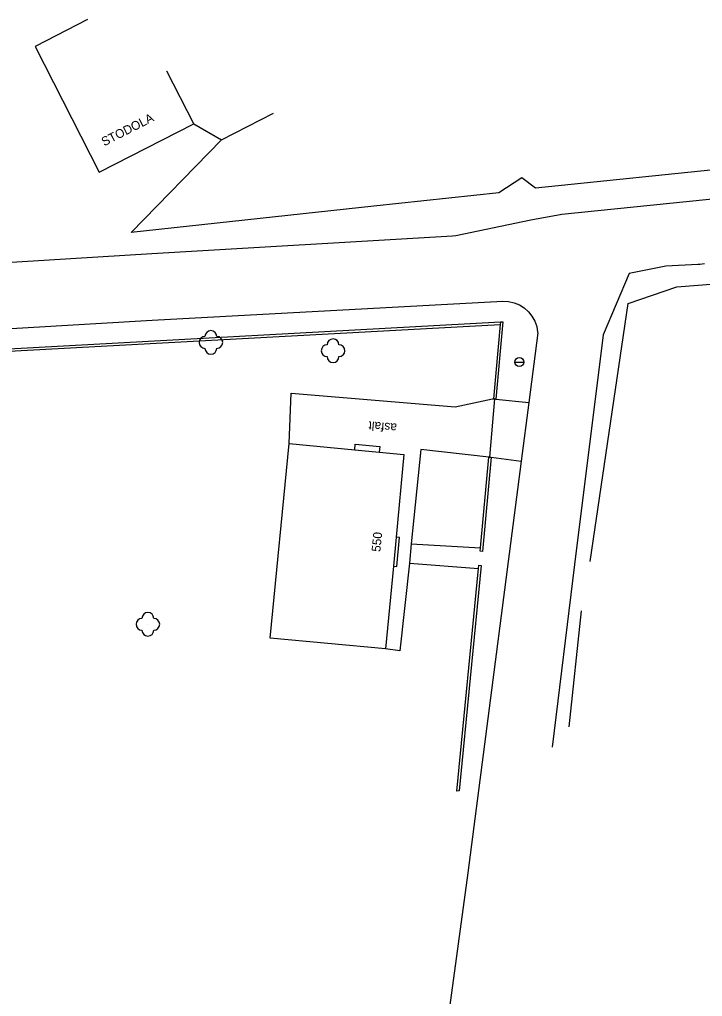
# Model space of a CAD drawing. Extents: x -536391 to -535419, y -1201788 to -1200779.
# Drawn here: x -535647.8 to -535590.1, y -1201668.6 to -1201586 of the extents above; entities that cross this region are included whole.
import ezdxf

# ---------------------------------------------------------------- set-up
doc = ezdxf.new("R2010")
doc.units = 0
for name, color, linetype in [('BUDOVY_MĚŘ', 7, 'Continuous'), ('POMOC_POPIS', 7, 'Continuous'), ('ROZHRANÍ_PLOCH', 7, 'Continuous'), ('ZELEŇ', 7, 'Continuous'), ('ZN_DOPLŇKOVÉ', 7, 'Continuous'), ('Č_POPIS_ORIENT', 7, 'Continuous')]:
    doc.layers.add(name, color=color, linetype=linetype)

msp = doc.modelspace()

# ---------------------------------------------------------------- linework, layer by layer
at = {"layer": 'BUDOVY_MĚŘ'}
for points in [[(-535642.06, -1201585.96), (-535646.51, -1201588.24), (-535641.1, -1201598.86), (-535633.08, -1201594.77)], [(-535633.08, -1201594.77), (-535635.36, -1201590.32)], [(-535616.86, -1201639.18), (-535626.62, -1201638.27), (-535625.02, -1201621.81)], [(-535625.02, -1201621.81), (-535619.47, -1201622.35)], [(-535619.47, -1201622.35), (-535617.4, -1201622.55)], [(-535617.4, -1201622.55), (-535615.32, -1201622.75), (-535615.98, -1201629.74)], [(-535615.98, -1201629.74), (-535616.21, -1201632.2)], [(-535616.21, -1201632.2), (-535616.86, -1201639.18)]]:
    msp.add_lwpolyline(points, dxfattribs=at)
at = {"layer": 'ROZHRANÍ_PLOCH'}
for points in [[(-535586.73, -1201600.91), (-535601.96, -1201602.45), (-535604.58, -1201602.94), (-535610.94, -1201604.25), (-535611.21, -1201604.27), (-535636.62, -1201605.79), (-535670.91, -1201607.88)], [(-535593.16, -1201606.83), (-535596.27, -1201607.45), (-535598.47, -1201612.63), (-535600.88, -1201632.06), (-535602.77, -1201647.49)], [(-535589.91, -1201606.63), (-535590.1, -1201606.65), (-535590.29, -1201606.67), (-535590.47, -1201606.69), (-535593.16, -1201606.83)], [(-535670.5, -1201613.38), (-535636.6, -1201611.38), (-535606.94, -1201609.77), (-535606.46, -1201609.81), (-535605.99, -1201609.92), (-535605.55, -1201610.1), (-535605.15, -1201610.35), (-535604.79, -1201610.67), (-535604.49, -1201611.05), (-535604.25, -1201611.46), (-535604.09, -1201611.92), (-535604.01, -1201612.39), (-535604, -1201612.47), (-535604.76, -1201618.34)], [(-535625.02, -1201621.81), (-535624.85, -1201617.57), (-535610.99, -1201618.72), (-535607.83, -1201618.05), (-535607.73, -1201618.04)], [(-535607.53, -1201618.06), (-535604.76, -1201618.34)], [(-535604.76, -1201618.34), (-535605.4, -1201623.3)], [(-535619.47, -1201622.35), (-535619.43, -1201621.87), (-535617.35, -1201622.07), (-535617.4, -1201622.55)], [(-535608.13, -1201622.96), (-535613.9, -1201622.33), (-535614.7, -1201630.29)], [(-535605.4, -1201623.3), (-535609.91, -1201658.13), (-535616.63, -1201707.41), (-535624.28, -1201765.57), (-535626.89, -1201785.62), (-535627.19, -1201786.05), (-535627.78, -1201786.76), (-535628.42, -1201787.43), (-535629.12, -1201788.03), (-535629.31, -1201788.17)], [(-535607.93, -1201622.98), (-535605.4, -1201623.3)], [(-535616.21, -1201632.2), (-535615.92, -1201632.23), (-535615.68, -1201629.77), (-535615.98, -1201629.74)], [(-535614.7, -1201630.29), (-535614.85, -1201631.95)], [(-535614.7, -1201630.29), (-535608.85, -1201630.64)], [(-535614.85, -1201631.95), (-535615.65, -1201639.36), (-535616.86, -1201639.18)], [(-535614.85, -1201631.95), (-535609.02, -1201632.39)]]:
    msp.add_lwpolyline(points, dxfattribs=at)
at = {"layer": 'ZELEŇ'}
for centre in [(-535631.64, -1201613.27), (-535621.31, -1201613.97), (-535636.97, -1201637.11)]:
    msp.add_circle(centre, 0.0005, dxfattribs=at)
for centre, start, end in [((-535631.64, -1201612.77), 0, 179.99999), ((-535632.14, -1201613.27), 89.99999, 269.99999), ((-535631.14, -1201613.27), 270, 89.99999), ((-535621.81, -1201613.97), 89.99999, 269.99999), ((-535621.31, -1201613.47), 0, 179.99999), ((-535620.81, -1201613.97), 270, 89.99999), ((-535631.64, -1201613.77), 179.99999, 359.99999), ((-535621.31, -1201614.47), 179.99999, 359.99999), ((-535637.47, -1201637.11), 89.99999, 269.99999), ((-535636.97, -1201636.61), 0, 179.99999), ((-535636.47, -1201637.11), 270, 89.99999), ((-535636.97, -1201637.61), 179.99999, 359.99999)]:
    msp.add_arc(centre, 0.5, start, end, dxfattribs=at)
at = {"layer": 'ZN_DOPLŇKOVÉ'}
msp.add_line((-535605.935, -1201614.93), (-535605.185, -1201614.93), dxfattribs=at)
for points in [[(-535572.12, -1201588.65), (-535571.35, -1201590.42), (-535577.76, -1201593.75), (-535587.2, -1201598.48), (-535604.18, -1201600.22)], [(-535630.75, -1201596.13), (-535626.34, -1201593.87)], [(-535633.08, -1201594.77), (-535630.75, -1201596.13)], [(-535604.18, -1201600.22), (-535605.35, -1201599.35), (-535607.29, -1201600.63), (-535617.85, -1201601.75), (-535638.39, -1201603.96), (-535630.75, -1201596.13)], [(-535592.23, -1201608.58), (-535584.33, -1201607.95), (-535556.13, -1201605.24)], [(-535599.58, -1201631.8), (-535596.35, -1201609.97), (-535592.23, -1201608.58)], [(-535649.24, -1201614.05), (-535607.18, -1201611.74)], [(-535649.22, -1201613.85), (-535607.16, -1201611.54)], [(-535607.18, -1201611.74), (-535607.73, -1201618.04)], [(-535607.16, -1201611.54), (-535606.96, -1201611.53), (-535607.53, -1201618.06)], [(-535607.16, -1201611.54), (-535607.18, -1201611.74)], [(-535608.04, -1201622.97), (-535607.64, -1201618.05)], [(-535607.73, -1201618.04), (-535607.64, -1201618.05)], [(-535607.53, -1201618.06), (-535607.64, -1201618.05)], [(-535607.93, -1201622.98), (-535608.68, -1201630.95), (-535608.88, -1201630.92), (-535608.85, -1201630.64)], [(-535608.85, -1201630.64), (-535608.13, -1201622.96)], [(-535608.13, -1201622.96), (-535608.04, -1201622.97)], [(-535608.04, -1201622.97), (-535607.93, -1201622.98)], [(-535610.64, -1201651.2), (-535610.84, -1201651.21), (-535609.02, -1201632.39)], [(-535609.02, -1201632.39), (-535608.99, -1201632.12), (-535608.79, -1201632.14), (-535610.64, -1201651.2)], [(-535601.35, -1201645.78), (-535600.29, -1201635.98)]]:
    msp.add_lwpolyline(points, dxfattribs=at)
msp.add_circle((-535605.56, -1201614.93), 0.375, dxfattribs=at)

# ---------------------------------------------------------------- texts
at = {"layer": 'POMOC_POPIS'}
for s, rotation, p in [('STODOLA', 27.04, (-535640.66, -1201596.69)), ('asfalt', 175.26, (-535615.89, -1201620.14))]:
    msp.add_text(s, height=0.75, rotation=rotation, dxfattribs=at).set_placement(p)
at = {"layer": 'Č_POPIS_ORIENT'}
msp.add_text('550', height=0.75, rotation=84.40001, dxfattribs=at).set_placement((-535617.31, -1201631.01))

doc.saveas('drawing.dxf')
